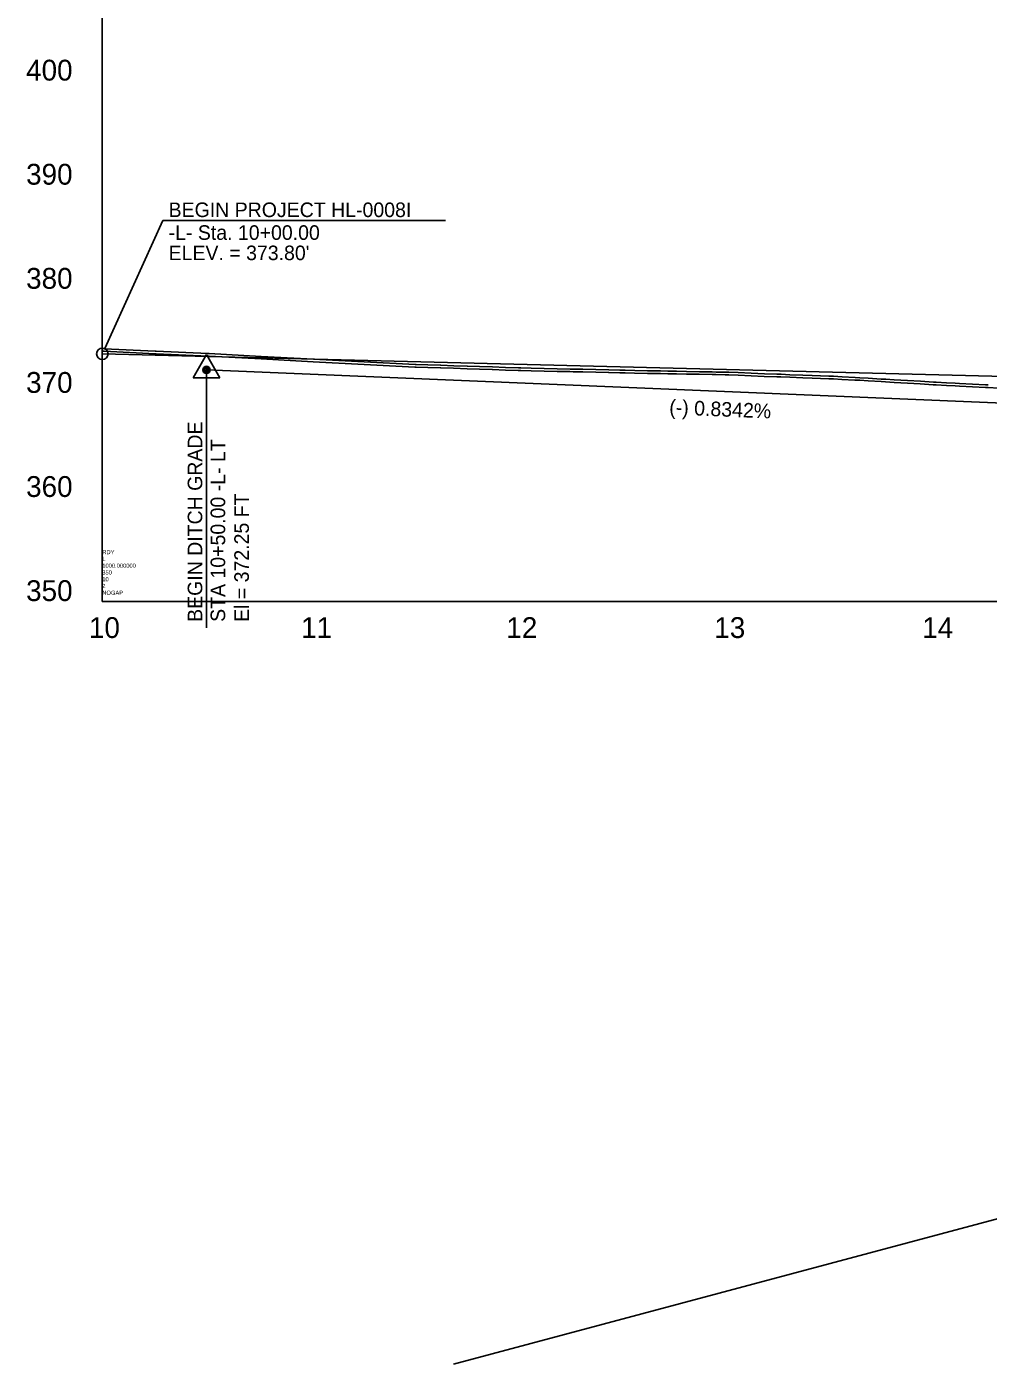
# Model space of a CAD drawing. Extents: x 1625686 to 1640492, y 1161393 to 1175642.
# Drawn here: x 1635876 to 1636337, y 1174544 to 1175187 of the extents above; entities that cross this region are included whole.
import ezdxf

# ---------------------------------------------------------------- set-up
doc = ezdxf.new("R2010")
doc.units = 0
for name, color, linetype in [('Exist Profile Cell', 7, 'Continuous'), ('Exist Vertical Profile Horizontal Axis Label Major', 7, 'Continuous'), ('Exist Vertical Profile Vertical Axis Label', 7, 'Continuous'), ('Prop Vertical Profile Ditch Grade Left', 7, 'Continuous'), ('Prop Vertical Profile Ditch Grade Left Label', 7, 'Continuous'), ('Prop Vertical Profile Grade', 7, 'Continuous'), ('Prop VPI Ditch Grade Left Label', 7, 'Continuous'), ('Prop VPI Label', 7, 'Continuous'), ('Scratch_Level_1', 7, 'Continuous'), ('Scratch_Level_3', 7, 'Continuous')]:
    doc.layers.add(name, color=color, linetype=linetype)

msp = doc.modelspace()

# ---------------------------------------------------------------- linework, layer by layer
at = {"layer": 'Exist Profile Cell'}
for q in [(1635911.78, 1175410.79), (1640378.1, 1174910.79), (1635911.78, 1174910.79)]:
    msp.add_line((1635911.78, 1174910.79), q, dxfattribs=at)
at = {"layer": 'Prop Vertical Profile Ditch Grade Left'}
msp.add_lwpolyline([(1635961.78, 1175022.04), (1636501.21, 1174999.54), (1636561.78, 1175011.65), (1636711.78, 1175019.79)], dxfattribs=at)
at = {"layer": 'Prop Vertical Profile Grade'}
msp.add_line((1635911.78, 1175029.79), (1636451.78, 1175016.31), dxfattribs=at)
at = {"layer": 'Prop VPI Ditch Grade Left Label'}
for p, q in [((1635961.78, 1175029.52), (1635955.33, 1175018.32)), ((1635961.78, 1175029.52), (1635968.28, 1175018.32)), ((1635955.33, 1175018.32), (1635968.28, 1175018.32)), ((1635961.78, 1175022.04), (1635961.78, 1174898.22))]:
    msp.add_line(p, q, dxfattribs=at)
for radius in [1.75, 1.2, 0.5]:
    msp.add_circle((1635961.78, 1175022.04), radius, dxfattribs=at)
at = {"layer": 'Prop VPI Label'}
for p, q in [((1635912.97, 1175032.27), (1635940.77, 1175093.75)), ((1635940.77, 1175093.75), (1636076.48, 1175093.75))]:
    msp.add_line(p, q, dxfattribs=at)
msp.add_circle((1635911.78, 1175029.79), 2.75, dxfattribs=at)
at = {"layer": 'Scratch_Level_1'}
for p, q in [((1635911.84, 1175031.05), (1635912.61, 1175031.01)), ((1635911.9, 1175032.3), (1635912.67, 1175032.26)), ((1635937.61, 1175029.83), (1635962.6, 1175028.66)), ((1635937.67, 1175031.08), (1635962.66, 1175029.91)), ((1636068.03, 1175023.23), (1636074.24, 1175023.03)), ((1636068.07, 1175024.48), (1636074.28, 1175024.28)), ((1636074.24, 1175023.03), (1636080.45, 1175022.83)), ((1636074.28, 1175024.28), (1636080.49, 1175024.08)), ((1636080.45, 1175022.83), (1636087.03, 1175022.61)), ((1636080.49, 1175024.08), (1636087.07, 1175023.86)), ((1636087.03, 1175022.61), (1636092.87, 1175022.42)), ((1636087.07, 1175023.86), (1636092.91, 1175023.67)), ((1636092.87, 1175022.42), (1636099.07, 1175022.21)), ((1636092.91, 1175023.67), (1636099.12, 1175023.46)), ((1636099.12, 1175023.46), (1636105.33, 1175023.26)), ((1636105.33, 1175023.26), (1636111.53, 1175023.05)), ((1636112.79, 1175023.02), (1636117.72, 1175022.9)), ((1636117.72, 1175022.9), (1636123.92, 1175022.76)), ((1636123.92, 1175022.76), (1636130.13, 1175022.62)), ((1636137.79, 1175022.45), (1636142.55, 1175022.34)), ((1636099.07, 1175022.21), (1636105.28, 1175022.01)), ((1636105.28, 1175022.01), (1636111.49, 1175021.8)), ((1636112.76, 1175021.77), (1636117.69, 1175021.65)), ((1636117.69, 1175021.65), (1636123.9, 1175021.51)), ((1636123.9, 1175021.51), (1636130.1, 1175021.37)), ((1636137.76, 1175021.2), (1636142.52, 1175021.09)), ((1636142.52, 1175021.09), (1636148.73, 1175020.94)), ((1636142.55, 1175022.34), (1636148.76, 1175022.19)), ((1636148.73, 1175020.94), (1636154.94, 1175020.8)), ((1636148.76, 1175022.19), (1636154.97, 1175022.05)), ((1636167.35, 1175020.53), (1636173.56, 1175020.41)), ((1636167.38, 1175021.78), (1636173.58, 1175021.66)), ((1636173.56, 1175020.41), (1636179.77, 1175020.29)), ((1636173.58, 1175021.66), (1636179.79, 1175021.54)), ((1636185.97, 1175020.18), (1636187.42, 1175020.15)), ((1636185.99, 1175021.43), (1636187.44, 1175021.4)), ((1636187.43, 1175020.15), (1636192.19, 1175020.06)), ((1636187.45, 1175021.4), (1636192.21, 1175021.31)), ((1636192.19, 1175020.06), (1636198.39, 1175019.94)), ((1636192.21, 1175021.31), (1636198.42, 1175021.19)), ((1636198.39, 1175019.94), (1636204.6, 1175019.82)), ((1636198.42, 1175021.19), (1636204.63, 1175021.07)), ((1636210.81, 1175019.71), (1636212.49, 1175019.68)), ((1636210.83, 1175020.96), (1636212.51, 1175020.93)), ((1636212.52, 1175019.68), (1636217.05, 1175019.49)), ((1636212.57, 1175020.93), (1636217.1, 1175020.74)), ((1636217.05, 1175019.49), (1636223.26, 1175019.23)), ((1636217.1, 1175020.74), (1636223.31, 1175020.48)), ((1636235.66, 1175018.76), (1636237.57, 1175018.7)), ((1636235.7, 1175020.01), (1636237.61, 1175019.95)), ((1636237.58, 1175018.7), (1636241.88, 1175018.52)), ((1636237.64, 1175019.95), (1636241.93, 1175019.77)), ((1636241.88, 1175018.52), (1636248.09, 1175018.26)), ((1636241.93, 1175019.77), (1636248.14, 1175019.51)), ((1636260.55, 1175017.82), (1636262.71, 1175017.75)), ((1636260.59, 1175019.07), (1636262.75, 1175019))]:
    msp.add_line(p, q, dxfattribs=at)
for points in [[(1635912.62, 1175031.01), (1635937.12, 1175029.86), (1635937.61, 1175029.83)], [(1635912.67, 1175032.26), (1635937.18, 1175031.1), (1635937.66, 1175031.08)], [(1635962.69, 1175029.91), (1635963.12, 1175029.88), (1635988.12, 1175028.56)], [(1635962.62, 1175028.66), (1635963.06, 1175028.63), (1635988.05, 1175027.31)], [(1635988.05, 1175027.31), (1636013.05, 1175025.98), (1636037.43, 1175024.71)], [(1635988.12, 1175028.56), (1636013.12, 1175027.23), (1636037.49, 1175025.96)], [(1636037.43, 1175024.71), (1636061.85, 1175023.44), (1636062.41, 1175023.41), (1636068.03, 1175023.23)], [(1636037.49, 1175025.96), (1636061.91, 1175024.69), (1636062.46, 1175024.66), (1636068.07, 1175024.48)], [(1636111.54, 1175023.05), (1636112.06, 1175023.03), (1636112.78, 1175023.02)], [(1636130.13, 1175022.62), (1636136.34, 1175022.48), (1636137.79, 1175022.45)], [(1636111.49, 1175021.8), (1636112.02, 1175021.78), (1636112.76, 1175021.77)], [(1636130.1, 1175021.37), (1636136.31, 1175021.23), (1636137.76, 1175021.2)], [(1636154.94, 1175020.8), (1636160.19, 1175020.67), (1636162.78, 1175020.62), (1636167.35, 1175020.53)], [(1636154.97, 1175022.05), (1636160.22, 1175021.92), (1636162.8, 1175021.87), (1636167.38, 1175021.78)], [(1636179.77, 1175020.29), (1636183.23, 1175020.22), (1636185.97, 1175020.18)], [(1636179.79, 1175021.54), (1636183.26, 1175021.47), (1636185.99, 1175021.43)], [(1636204.6, 1175019.82), (1636206.41, 1175019.78), (1636210.81, 1175019.71)], [(1636204.63, 1175021.07), (1636206.43, 1175021.03), (1636210.83, 1175020.96)], [(1636223.26, 1175019.23), (1636229.6, 1175018.96), (1636235.66, 1175018.76)], [(1636223.31, 1175020.48), (1636229.65, 1175020.21), (1636235.7, 1175020.01)], [(1636248.09, 1175018.26), (1636252.51, 1175018.07), (1636260.55, 1175017.82)], [(1636248.14, 1175019.51), (1636252.56, 1175019.32), (1636260.59, 1175019.07)], [(1636262.74, 1175017.75), (1636266.85, 1175017.53), (1636273.12, 1175017.19), (1636275.41, 1175017.07)], [(1636262.81, 1175019), (1636266.92, 1175018.78), (1636273.18, 1175018.44), (1636275.47, 1175018.32)], [(1636275.42, 1175017.07), (1636279.4, 1175016.82), (1636285.66, 1175016.43), (1636287.81, 1175016.29), (1636291.92, 1175016.07), (1636298.31, 1175015.73)], [(1636275.5, 1175018.32), (1636279.47, 1175018.07), (1636285.74, 1175017.67), (1636287.88, 1175017.54), (1636291.99, 1175017.32), (1636298.37, 1175016.98)], [(1636298.4, 1175016.97), (1636304.55, 1175016.58), (1636310.81, 1175016.19), (1636312.11, 1175016.11), (1636317.05, 1175015.85), (1636321.3, 1175015.64), (1636323.32, 1175015.54), (1636329.58, 1175015.23), (1636335.85, 1175014.92), (1636337.1, 1175014.86)], [(1636298.32, 1175015.73), (1636304.47, 1175015.34), (1636310.74, 1175014.94), (1636312.04, 1175014.86), (1636316.99, 1175014.61), (1636321.24, 1175014.39), (1636323.25, 1175014.29), (1636329.52, 1175013.98), (1636335.79, 1175013.67), (1636337.04, 1175013.61)], [(1636337.04, 1175013.61), (1636342.06, 1175013.36), (1636344.68, 1175013.23), (1636348.32, 1175013.05), (1636354.59, 1175012.74), (1636360.86, 1175012.44), (1636361.39, 1175012.41), (1636367.11, 1175012.23), (1636368.03, 1175012.2)]]:
    msp.add_lwpolyline(points, dxfattribs=at)
for centre, radius, start, end in [((1635912.56, 1175029.76), 1.25, 87.29654, 87.32275), ((1635912.56, 1175029.76), 2.5, 87.29654, 87.32275), ((1635937.55, 1175028.59), 1.25, 87.30665, 87.47574), ((1635937.55, 1175028.59), 2.5, 87.30665, 87.47574), ((1635962.55, 1175027.41), 2.5, 86.76168, 87.30665), ((1635962.55, 1175027.41), 1.25, 86.76168, 87.30665), ((1635987.99, 1175026.06), 1.25, 86.95518, 86.96644), ((1635987.99, 1175026.06), 2.5, 86.95518, 86.96644), ((1636037.36, 1175023.46), 1.25, 87.0193, 87.02789), ((1636037.36, 1175023.46), 2.5, 87.0193, 87.02789), ((1636067.99, 1175021.98), 1.25, 88.14287, 88.15128), ((1636067.99, 1175021.98), 2.5, 88.14287, 88.15128), ((1636074.2, 1175021.78), 1.25, 88.13445, 88.14287), ((1636074.2, 1175021.78), 2.5, 88.13445, 88.14287), ((1636080.41, 1175021.58), 1.25, 88.12217, 88.13445), ((1636080.41, 1175021.58), 2.5, 88.12217, 88.13445), ((1636086.99, 1175021.36), 1.25, 88.11008, 88.12217), ((1636086.99, 1175021.36), 2.5, 88.11008, 88.12217), ((1636092.82, 1175021.17), 1.25, 88.10141, 88.11008), ((1636092.82, 1175021.17), 2.5, 88.10141, 88.11008), ((1636099.03, 1175020.97), 2.5, 88.09275, 88.10141), ((1636105.24, 1175020.76), 2.5, 88.08216, 88.09275), ((1636111.45, 1175020.55), 2.5, 88.00509, 88.08216), ((1636112.73, 1175020.52), 2.5, 88.70093, 88.76492), ((1636117.66, 1175020.4), 2.5, 88.69202, 88.70093), ((1636123.87, 1175020.26), 2.5, 88.68311, 88.69202), ((1636130.08, 1175020.12), 2.5, 88.67538, 88.68311), ((1636137.73, 1175019.95), 2.5, 88.68226, 88.80915), ((1636099.03, 1175020.97), 1.25, 88.09275, 88.10141), ((1636105.24, 1175020.76), 1.25, 88.08216, 88.09275), ((1636111.45, 1175020.55), 1.25, 88.00509, 88.08216), ((1636112.73, 1175020.52), 1.25, 88.70093, 88.76492), ((1636117.66, 1175020.4), 1.25, 88.69202, 88.70093), ((1636123.87, 1175020.26), 1.25, 88.68311, 88.69202), ((1636130.08, 1175020.12), 1.25, 88.67538, 88.68311), ((1636137.73, 1175019.95), 1.25, 88.68226, 88.80915), ((1636142.49, 1175019.84), 1.25, 88.6738, 88.68226), ((1636142.49, 1175019.84), 2.5, 88.6738, 88.68226), ((1636148.7, 1175019.69), 1.25, 88.66535, 88.6738), ((1636148.7, 1175019.69), 2.5, 88.66535, 88.6738), ((1636154.91, 1175019.55), 1.25, 88.6569, 88.66535), ((1636154.91, 1175019.55), 2.5, 88.6569, 88.66535), ((1636167.33, 1175019.28), 1.25, 88.88406, 88.89209), ((1636167.33, 1175019.28), 2.5, 88.88406, 88.89209), ((1636173.54, 1175019.16), 1.25, 88.87604, 88.88406), ((1636173.54, 1175019.16), 2.5, 88.87604, 88.88406), ((1636179.74, 1175019.04), 1.25, 88.86802, 88.87604), ((1636179.74, 1175019.04), 2.5, 88.86802, 88.87604), ((1636185.95, 1175018.93), 1.25, 89.07969, 89.08707), ((1636185.95, 1175018.93), 2.5, 89.07969, 89.08707), ((1636187.4, 1175018.9), 1.25, 88.88163, 89.07969), ((1636187.4, 1175018.9), 2.5, 88.88163, 89.07969), ((1636192.16, 1175018.81), 1.25, 88.87428, 88.88163), ((1636192.16, 1175018.81), 2.5, 88.87428, 88.88163), ((1636198.37, 1175018.69), 1.25, 88.86693, 88.87428), ((1636198.37, 1175018.69), 2.5, 88.86693, 88.87428), ((1636204.58, 1175018.57), 1.25, 88.85959, 88.86693), ((1636204.58, 1175018.57), 2.5, 88.85959, 88.86693), ((1636210.79, 1175018.46), 1.25, 89.06705, 89.07378), ((1636210.79, 1175018.46), 2.5, 89.06705, 89.07378), ((1636212.47, 1175018.43), 1.25, 87.58707, 89.06705), ((1636212.47, 1175018.43), 2.5, 87.58707, 89.06705), ((1636217, 1175018.24), 1.25, 87.58054, 87.58707), ((1636217, 1175018.24), 2.5, 87.58054, 87.58707), ((1636223.2, 1175017.98), 1.25, 87.57386, 87.58054), ((1636223.2, 1175017.98), 2.5, 87.57386, 87.58054), ((1636235.62, 1175017.51), 1.25, 88.13651, 88.14138), ((1636235.62, 1175017.51), 2.5, 88.13651, 88.14138), ((1636237.53, 1175017.45), 1.25, 87.60877, 88.13651), ((1636237.53, 1175017.45), 2.5, 87.60877, 88.13651), ((1636241.83, 1175017.27), 1.25, 87.60397, 87.60877), ((1636241.83, 1175017.27), 2.5, 87.60397, 87.60877), ((1636248.04, 1175017.01), 1.25, 87.59918, 87.60397), ((1636248.04, 1175017.01), 2.5, 87.59918, 87.60397), ((1636260.51, 1175016.57), 1.25, 88.16201, 88.18166), ((1636260.51, 1175016.57), 2.5, 88.16201, 88.18166), ((1636262.67, 1175016.5), 1.25, 86.94418, 88.16201), ((1636262.67, 1175016.5), 2.5, 86.94418, 88.16201), ((1636275.34, 1175015.82), 1.25, 86.3968, 86.95018), ((1636275.34, 1175015.82), 2.5, 86.3968, 86.95018), ((1636298.24, 1175014.48), 2.5, 86.36937, 86.91874), ((1636298.24, 1175014.48), 1.25, 86.36937, 86.91874), ((1636336.98, 1175012.36), 1.25, 87.10527, 87.19134), ((1636336.98, 1175012.36), 2.5, 87.10527, 87.19134)]:
    msp.add_arc(centre, radius, start, end, dxfattribs=at)
at = {"layer": 'Scratch_Level_3'}
msp.add_line((1636080.34, 1174544.46), (1640138.71, 1175631), dxfattribs=at)
msp.add_lwpolyline([(1635911.78, 1174910.79), (1640049.19, 1174910.79), (1640049.19, 1175362.47)], dxfattribs=at)

# ---------------------------------------------------------------- texts
at = {"layer": 'Exist Profile Cell'}
for s, p in [('RDY', (1635911.78, 1174933.54)), ('1000.000000', (1635911.78, 1174927.04)), ('L', (1635911.78, 1174930.29)), ('350', (1635911.78, 1174923.79)), ('10', (1635911.78, 1174920.54)), ('2', (1635911.78, 1174917.29)), ('NOGAP', (1635911.78, 1174914.04))]:
    msp.add_text(s, height=2, dxfattribs=at).set_placement(p)
at = {"layer": 'Exist Vertical Profile Horizontal Axis Label Major'}
for s, p in [('10', (1635905.37, 1174893.29)), ('11', (1636007.2, 1174893.29)), ('12', (1636105.75, 1174893.29)), ('13', (1636205.59, 1174893.29)), ('14', (1636305.43, 1174893.29))]:
    msp.add_text(s, height=10, dxfattribs=at).set_placement(p)
at = {"layer": 'Exist Vertical Profile Vertical Axis Label'}
for s, p in [('400', (1635875.21, 1175161.04)), ('390', (1635875.21, 1175111.04)), ('380', (1635875.21, 1175061.04)), ('370', (1635875.21, 1175011.04)), ('360', (1635875.21, 1174961.04)), ('350', (1635875.21, 1174911.04))]:
    msp.add_text(s, height=10, dxfattribs=at).set_placement(p)
at = {"layer": 'Prop Vertical Profile Ditch Grade Left Label'}
msp.add_text('(-) 0.8342%', height=7, rotation=357.61154, dxfattribs=at).set_placement((1636183.87, 1175000.76))
at = {"layer": 'Prop VPI Ditch Grade Left Label'}
for s, p in [('BEGIN DITCH GRADE', (1635959.78, 1174901.04)), ('STA 10+50.00 -L- LT', (1635970.78, 1174901.04)), ('El = 372.25 FT', (1635982.16, 1174901.04))]:
    msp.add_text(s, height=7, rotation=90, dxfattribs=at).set_placement(p)
at = {"layer": 'Prop VPI Label'}
for s, p in [('BEGIN PROJECT HL-0008I', (1635943.61, 1175095.47)), ('-L- Sta. 10+00.00', (1635943.61, 1175084.53)), ("ELEV. = 373.80'", (1635943.61, 1175074.78))]:
    msp.add_text(s, height=7, dxfattribs=at).set_placement(p)

doc.saveas('drawing.dxf')
